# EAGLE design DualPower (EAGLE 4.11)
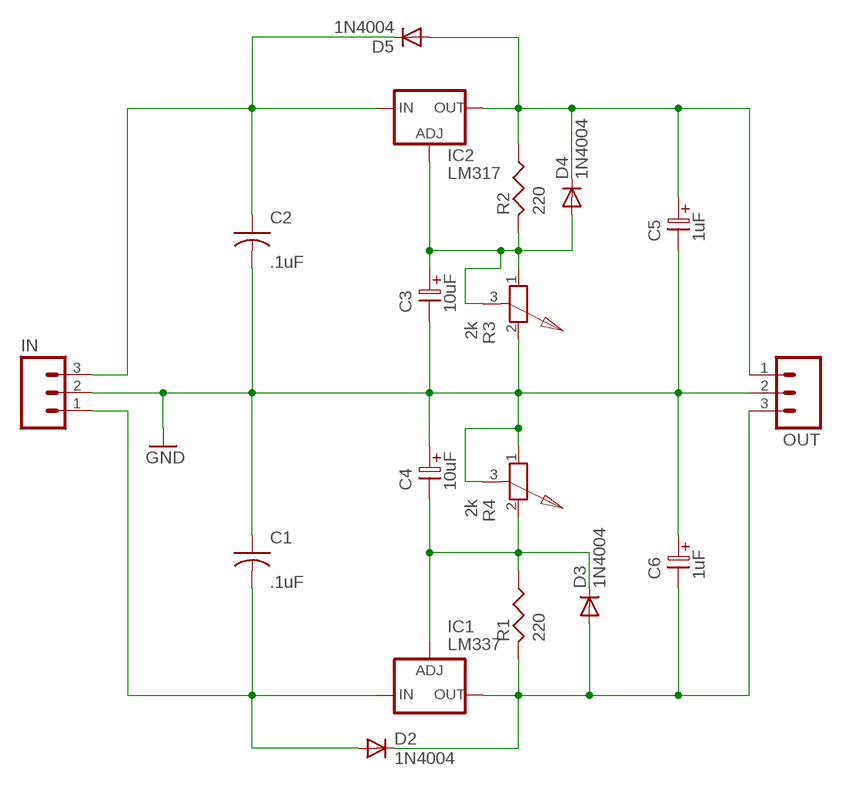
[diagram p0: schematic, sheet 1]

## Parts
C1  .1uF  CAP-5  [C-5]
C2  .1uF  CAP-5  [C-5]
C3  10uF  ELC-2,5L  [ES-2,5L]
C4  10uF  ELC-2,5L  [ES-2,5L]
C5  1uF  ELC-2,5L  [ES-2,5L]
C6  1uF  ELC-2,5L  [ES-2,5L]
D2  1N4004  [DO41-10]
D3  1N4004  [DO41-10]
D4  1N4004  [DO41-10]
D5  1N4004  [DO41-10]
IC1  LM337  LM337-TO3  [TO3-K02]
IC2  LM317  LM317-TO3  [TO3-K02]
IN  M03  [03P]
OUT  M03  [03P]
R1  220  RESUS-10  [R-10]
R2  220  RESUS-10  [R-10]
R3  2k  POT-TRIM  [PT-SPIN]
R4  2k  POT-TRIM  [PT-SPIN]

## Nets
GND: C1.1 C2.2 C3.2 C4.1 C5.2 C6.1 IN.2 OUT.2 R3.2 R4.1 R4.3
NEGADJ: C4.2 D3.C IC1.2(ADJ) R1.1 R4.2
NEGIN: C1.2 D2.A IC1.3(IN) IN.1
NEGOUT: C6.2 D2.C D3.A IC1.1(OUT) OUT.3 R1.2
POSADJ: C3.1 D4.A IC2.2(ADJ) R2.2 R3.1 R3.3
POSIN: C2.1 D5.C IC2.1(IN) IN.3
POSOUT: C5.1 D4.C D5.A IC2.3(OUT) OUT.1 R2.1

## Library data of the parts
C1 C2 = discrete:CAP-5
C3-C6 = discrete:ELC-2,5L
D2-D5 = diode:1N4004: DIODE
IC1 = v-reg:LM337-TO3: VOLTAGE REGULATOR
IC2 = v-reg:LM317-TO3: VOLTAGE REGULATOR
IN OUT = con-amp-quick:M03: AMP QUICK CONNECTOR
R1 R2 = discrete:RESUS-10
R3 R4 = discrete:POT-TRIM

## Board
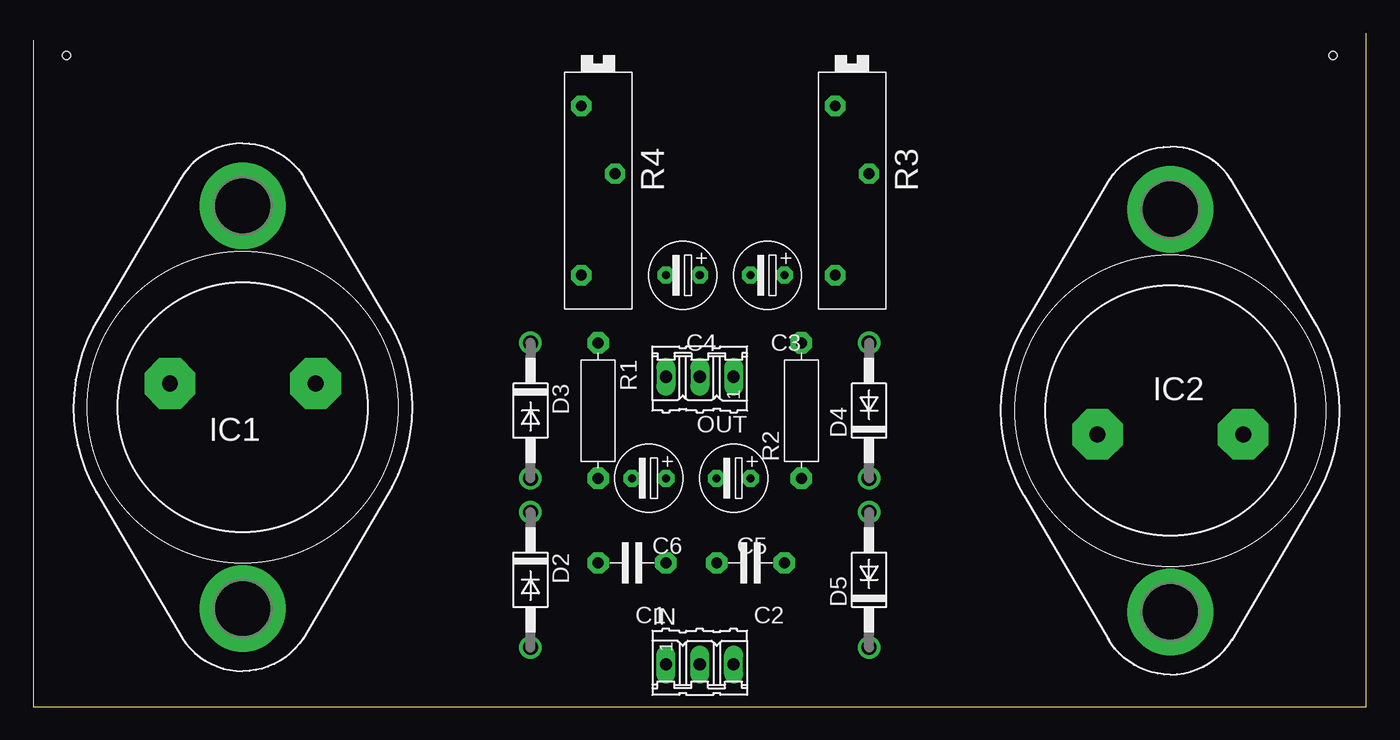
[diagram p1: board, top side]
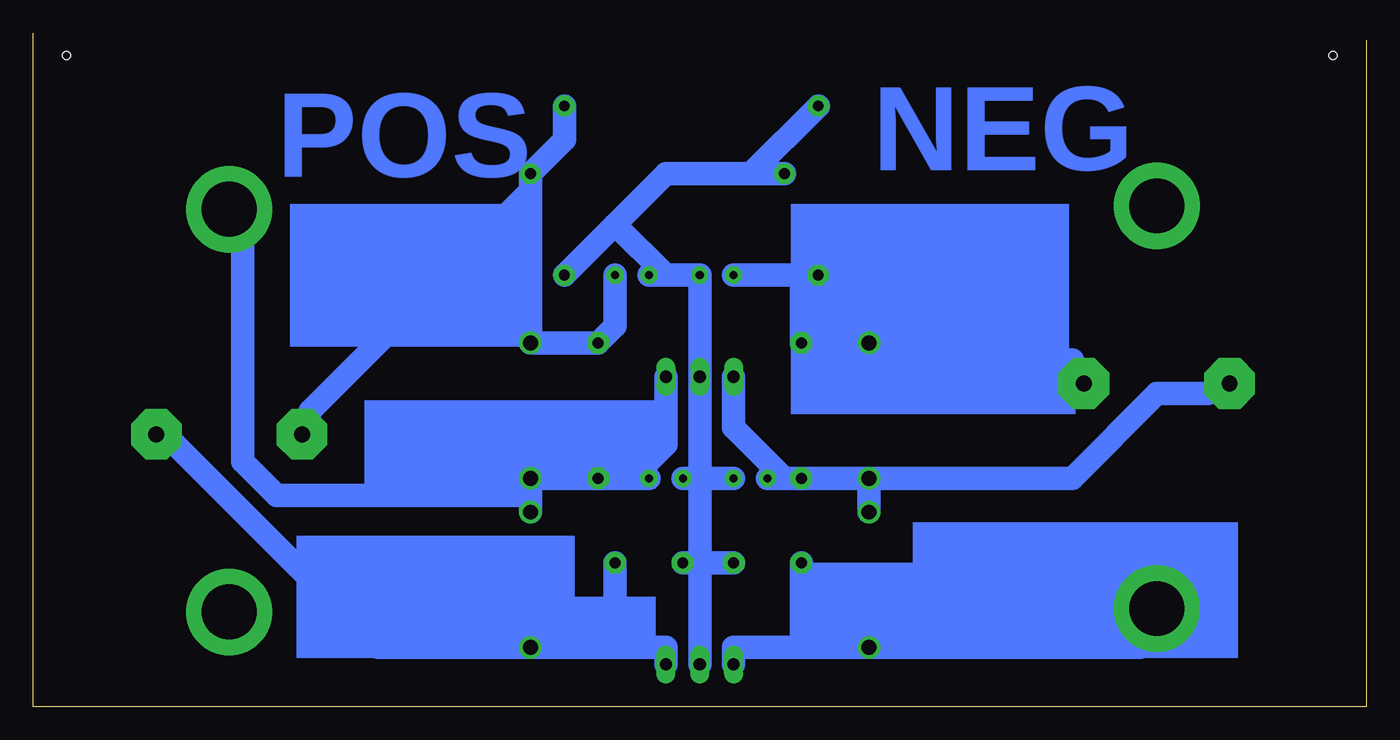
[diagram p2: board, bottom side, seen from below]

Size 100 x 50.54 mm. Coordinates in mm from the lower left corner, seen from the top.
Outline: 100,50.54 100,0 0,0 0,50.03
Copper layers (1*16): Top 0.035mm / dielectric 1.5mm / Bottom 0.035mm
Design rules "default": minimum track width 70mil, minimum drill 32mil, track to track 28mil, track to pad 28mil, pad to pad 8mil, via to via 8mil, smd to smd 8mil, copper to edge 20mil, drill to drill 18mil, minimum pad ring 10mil, minimum via ring 8mil, stop-mask expansion 4mil, vias tented up to drill 0mil, thermal gap 10mil
Holes 0.61 mm at 2.5,48.89 97.5,48.89

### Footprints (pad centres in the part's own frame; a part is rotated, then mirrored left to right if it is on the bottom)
C-5 = drill 0.813 pad 1.6 octagon: 1 -2.54,0; 2 2.54,0
ES-2,5L = drill 0.61 pad 1.27 octagon: 1 0,0; 2 2.54,0
DO41-10 = drill 1.118 round: A 5.08,0; C -5.08,0
TO3-K02 = drill 1.194 pad 3.81 octagon: 1 -1.778,-5.461; 2 -1.778,5.461 | drill 4.115 pad 6.477 round: 3 15.113,0; 3@ -15.113,0
03P = drill 0.914 long: 1 -2.54,0; 2 0,0; 3 2.54,0
R-10 = drill 0.813 pad 1.6 octagon: 1 -5.08,0; 2 5.08,0
PT-SPIN = drill 0.813 pad 1.524 octagon: 1 -6.35,-1.27; 2 6.35,-1.27; 3 -1.27,1.27

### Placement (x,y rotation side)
C1  44.92,10.79 180 top
C2  53.81,10.79 180 top
C3  56.35,32.38 180 top
C4  50,32.38 180 top
C5  53.81,17.14 180 top
C6  47.46,17.14 180 top
D2  37.3,9.52 270 top
D3  37.3,22.22 270 top
D4  62.7,22.22 90 top
D5  62.7,9.52 90 top
IC1  15.71,22.47 270 top
IC2  85.31,22.22 90 top
IN  50,3.17 0 top
OUT  50,24.76 180 top
R1  42.38,22.22 270 top
R2  57.62,22.22 90 top
R3  61.43,38.73 270 top
R4  42.38,38.73 270 top

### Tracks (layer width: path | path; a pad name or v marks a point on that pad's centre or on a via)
GND
  Bottom 1.778: 56.35,36.19 52.54,40 46.19,40 | 56.35,36.19 R3.2 | 46.19,40 R4.3 | 46.19,40 R4.1 | 52.54,32.38 C3.2 | 52.54,32.38 C4.1 OUT.2 50,17.14 | 50,17.14 C5.2 | 50,17.14 C6.1 | 50,10.79 50,17.14 | IN.2 50,10.79 | 50,10.79 C1.1 | 50,10.79 C2.2 | 52.54,32.38 56.35,36.19
NEGADJ
  Bottom 1.778: 42.38,32.38 R4.2 | 42.38,32.38 C4.2 | 42.38,32.38 R1.1 D3.C 36.03,26.03 22.06,26.03 IC1.2
NEGIN
  Bottom 1.778: 42.38,4.44 D2.A 16.98,4.44 IC1.3 | 42.38,4.44 47.46,4.44 IN.1 | 42.38,4.44 C1.2
NEGOUT
  Bottom 1.778: D3.A D2.C | 43.65,17.14 R1.2 D3.A | 43.65,17.14 C6.2 | 43.65,17.14 47.46,20.95 OUT.3 | D3.A 22.06,17.14 15.71,23.49 11.9,23.49 IC1.1
POSADJ
  Bottom 1.778: C3.1 56.35,28.57 R2.2 D4.A 62.7,38.73 | 62.7,38.73 R3.3 60.16,42.54 R3.1 | 62.7,38.73 79.21,22.22 IC2.2
POSIN
  Bottom 1.778: 56.35,4.44 D5.C 74.13,4.44 89.37,19.68 IC2.1 | 56.35,4.44 52.54,4.44 IN.3 | 56.35,4.44 C2.1
POSOUT
  Bottom 1.778: 62.7,15.87 D4.C R2.1 55.08,17.14 | 62.7,15.87 D5.A | C5.1 55.08,17.14 | 55.08,17.14 52.54,19.68 OUT.1 | 62.7,15.87 81.75,15.87 84.29,18.41 84.29,34.92 IC2.3
(copper drawn outside any net)
  shapes: Bottom area x8

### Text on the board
Bottom: NEG | POS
